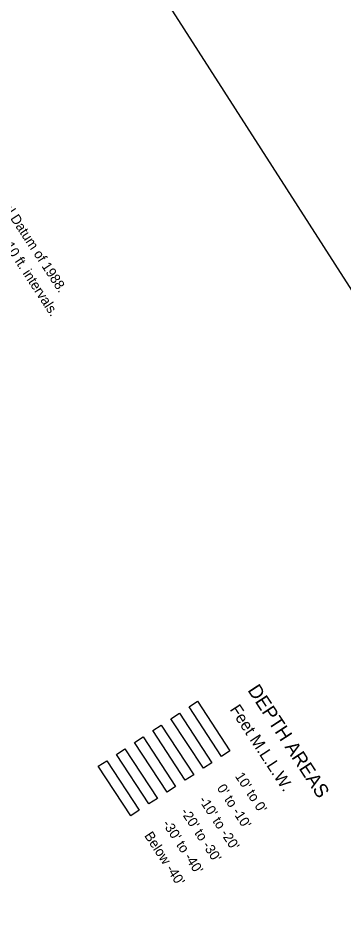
# Model space of a CAD drawing. Extents: x 3945642 to 3966284, y 206476 to 228921.
# Drawn here: x 3949497 to 3950869, y 217128 to 220977 of the extents above; entities that cross this region are included whole.
import ezdxf

# ---------------------------------------------------------------- set-up
doc = ezdxf.new("R2010")
doc.units = 0
for name, color, linetype in [('V-ANNO-NOTE', 7, 'Continuous'), ('V-GRID-FRAM', 7, 'Continuous'), ('V-TOPO-DPTH', 7, 'Continuous')]:
    doc.layers.add(name, color=color, linetype=linetype)

msp = doc.modelspace()

# ---------------------------------------------------------------- linework, layer by layer
at = {"layer": 'V-GRID-FRAM'}
msp.add_lwpolyline([(3956475, 226502.1), (3964764.2, 213849), (3957669.1, 209282.6), (3949512, 222000.5), (3956475, 226502.1)], dxfattribs=at)
at = {"layer": 'V-TOPO-DPTH'}
for points in [[(3950252.6, 218095.6), (3950389.6, 217886.5), (3950354.1, 217863.2), (3950217.1, 218072.3)], [(3950176.1, 218045.5), (3950313.1, 217836.4), (3950277.5, 217813.1), (3950140.5, 218022.2)], [(3950099.6, 217995.3), (3950236.6, 217786.2), (3950201, 217762.9), (3950064, 217972.1)], [(3950023, 217945.2), (3950160, 217736.1), (3950124.5, 217712.8), (3949987.5, 217921.9)], [(3949946.5, 217895.1), (3950083.5, 217685.9), (3950047.9, 217662.6), (3949910.9, 217871.8)], [(3949869.9, 217844.9), (3950006.9, 217635.8), (3949971.4, 217612.5), (3949834.4, 217821.6)]]:
    msp.add_lwpolyline(points, close=True, dxfattribs=at)

# ---------------------------------------------------------------- texts
at = {"layer": 'V-ANNO-NOTE'}
for s, p in [('All elevations are expressed in feet and refer to North American Vertical Datum of 1988.', (3948488.1, 221618.9)), ('Contours below Low Water Reference Plane are expressed in feet at 5 and 10 ft. intervals.', (3948418.4, 221573.2))]:
    msp.add_text(s, height=41.5, rotation=303.2293, dxfattribs=at).set_placement(p)
at = {"layer": 'V-TOPO-DPTH'}
for s, height, p in [('DEPTH AREAS', 58.35, (3950461.9, 218142.7)), ('Feet M.L.L.W.', 50, (3950387.1, 218061.5)), ("10' to 0'", 41.5, (3950409.3, 217779.8)), ("0' to -10'", 41.5, (3950332.8, 217729.7)), ("-10' to -20'", 41.5, (3950256.2, 217679.6)), ("-20' to -30'", 41.5, (3950179.7, 217629.4)), ("-30' to -40'", 41.5, (3950103.1, 217579.3)), ("Below -40'", 41.5, (3950026.6, 217529.1))]:
    msp.add_text(s, height=height, rotation=303.2293, dxfattribs=at).set_placement(p)

doc.saveas('drawing.dxf')
